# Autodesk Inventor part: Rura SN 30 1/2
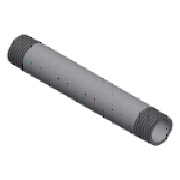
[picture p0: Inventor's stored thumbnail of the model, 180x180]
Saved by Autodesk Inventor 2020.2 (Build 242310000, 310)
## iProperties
Manager: www.cadconsulting.pl
Company: Fabian Stasiak CAD Consulting
Created: 2014-08
Part Number: Rura SN 30 1/2
Material: Ogólny
Document SubType Name: Modeling
Standard: KeroX 123
Designer: F.Stasiak
Manufacturer: KeroX
Language: pl-PL
Size Designation: 1/2-30-5
Categories: <MemberInstance><Categories><Category DisplayName="Rury cienko- i grubościenne" InternalName="4347fa0f-2144-441d-94cd-e3e15c92b736" Mnemonic="TUBEANDPIPE"><Cate
Density: 1 g/cm^3
Appearance: Domyślna
Catalog Web Link: www.expertbooks.pl
IsCustomPart: 0
Author: F.Stasiak
Subject: Zbiór ćwiczeń. Autodesk Inventor 2020. Kurs Professional
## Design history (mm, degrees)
sketch "Szkic1"
  geometry: L1 (0, 8.255)-(127, 8.255); L2 (127, 8.255)-(127, 10.247); L3 (0, 10.247)-(0, 8.255); L4 (0, 0)-(127, 0); L5 (0, 10.247)-(13.462, 10.668); L6 (13.462, 10.668)-(113.538, 10.668); L7 (113.538, 10.668)-(127, 10.247); L8 (0, 0)-(0, 8.255); L9 (127, 8.255)-(127, 0); L10 (13.462, 10.668)-(13.462, 0); L11 (113.538, 10.668)-(113.538, 0)
  constraints: 22 end point, 3 horizontal, 3 perpendicular, 2 equal length, 2 point on line, 2 vertical, 1 parallel
  dimensions: "d1" = 1.79 deg angle of L5 L6; "LG" = 13.462 distance between parallel lines of L10 L8; "ID" = 16.51 diameter of L1 L4; "OD" = 21.336 diameter of L6 L4; "PL" = 127 distance of L4.start L4.end
revolve "Obrót1" sketch "Szkic1" stored, may be unused: angle "d6" = 90 deg
feature "Gwint1" dims "d7" = 19.8628, "d8" = 0
feature "Gwint2" dims "d9" = 19.8628, "d10" = 0
node "Płaszczyzna konstrukcyjna1"
node "Oś konstrukcyjna1"
node "Punkt konstrukcyjny1"
  node "Płaszczyzna konstrukcyjna2"
node "Punkt konstrukcyjny2"
node "Punkt konstrukcyjny3"
node "Punkt konstrukcyjny4"
node "Oś konstrukcyjna2"
node "Oś konstrukcyjna3"
node "Punkt konstrukcyjny5"
node "Punkt konstrukcyjny6"
node "Bryła1"
other parameters: "d11" = -13.462 (= -LG), "d12" = -13.462 (= -LG)
